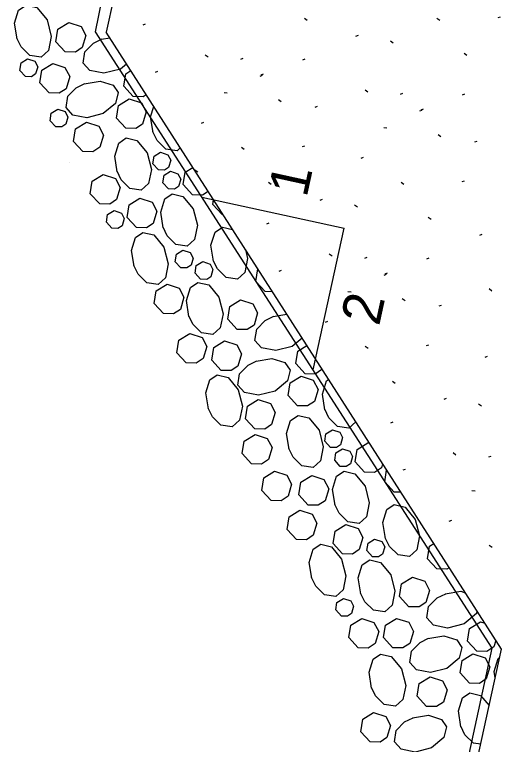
# Model space of a CAD drawing. Extents: x 2126110 to 2128246, y 1804858 to 1811658.
# Drawn here: x 2126783.7 to 2126845.4, y 1806501.5 to 1806594 of the extents above; entities that cross this region are included whole.
import ezdxf

# ---------------------------------------------------------------- set-up
doc = ezdxf.new("R2010")
doc.units = 0
doc.layers.add('1', color=7, linetype='Continuous')

msp = doc.modelspace()

# ---------------------------------------------------------------- linework, layer by layer
at = {"layer": '1'}
for p, q in [((2126793.902, 1806591.798), (2126800.031, 1806621.151)), ((2126801.607, 1806620.821), (2126795.259, 1806591.77)), ((2126820.761, 1806593.22), (2126820.408, 1806593.479)), ((2126837.578, 1806593.226), (2126837.226, 1806593.485)), ((2126844.984, 1806593.608), (2126845.283, 1806593.724)), ((2126799.944, 1806592.682), (2126800.242, 1806592.798)), ((2126844.245, 1806513.73), (2126793.902, 1806591.798)), ((2126845.409, 1806513.574), (2126795.259, 1806591.77)), ((2126794.663, 1806590.879), (2126795.72, 1806591.052)), ((2126826.961, 1806591.261), (2126827.259, 1806591.378)), ((2126831.684, 1806590.379), (2126831.331, 1806590.637)), ((2126808.202, 1806588.602), (2126807.849, 1806588.861)), ((2126841.023, 1806588.792), (2126840.671, 1806589.051)), ((2126812.358, 1806588.355), (2126812.657, 1806588.472)), ((2126820.207, 1806588.254), (2126820.505, 1806588.371)), ((2126801.508, 1806586.709), (2126801.806, 1806586.825)), ((2126814.813, 1806586.202), (2126815.111, 1806586.319)), ((2126814.95, 1806586.354), (2126815.248, 1806586.471)), ((2126810.224, 1806584.103), (2126810.624, 1806584.061)), ((2126828.465, 1806584.174), (2126828.112, 1806584.433)), ((2126832.621, 1806583.927), (2126832.919, 1806584.044)), ((2126817.469, 1806582.94), (2126817.117, 1806583.199)), ((2126840.469, 1806583.826), (2126840.768, 1806583.943)), ((2126821.771, 1806582.281), (2126822.069, 1806582.398)), ((2126835.076, 1806581.775), (2126835.374, 1806581.891)), ((2126835.212, 1806581.926), (2126835.511, 1806582.043)), ((2126807.355, 1806580.231), (2126807.653, 1806580.347)), ((2126830.486, 1806579.675), (2126830.886, 1806579.633)), ((2126837.732, 1806578.512), (2126837.379, 1806578.771)), ((2126842.033, 1806577.853), (2126842.332, 1806577.97)), ((2126812.775, 1806576.876), (2126812.422, 1806577.135)), ((2126820.181, 1806577.257), (2126820.479, 1806577.374)), ((2126827.618, 1806575.803), (2126827.916, 1806575.919)), ((2126790.616, 1806575.194), (2126790.628, 1806575.2)), ((2126806.881, 1806574.028), (2126806.528, 1806574.287)), ((2126840.444, 1806572.829), (2126840.742, 1806572.946)), ((2126816.22, 1806572.442), (2126815.868, 1806572.7)), ((2126833.038, 1806572.448), (2126832.685, 1806572.707)), ((2126807.4, 1806570.866), (2126825.446, 1806566.922)), ((2126822.42, 1806570.483), (2126822.719, 1806570.599)), ((2126827.143, 1806569.6), (2126826.791, 1806569.859)), ((2126810.091, 1806568.644), (2126809.99, 1806568.646)), ((2126815.666, 1806567.476), (2126815.964, 1806567.592)), ((2126836.483, 1806568.014), (2126836.13, 1806568.273)), ((2126821.523, 1806548.966), (2126825.446, 1806566.922)), ((2126842.683, 1806566.055), (2126842.981, 1806566.172)), ((2126823.924, 1806563.396), (2126823.572, 1806563.654)), ((2126828.08, 1806563.149), (2126828.379, 1806563.265)), ((2126835.929, 1806563.048), (2126836.227, 1806563.164)), ((2126817.23, 1806561.503), (2126817.529, 1806561.619)), ((2126830.535, 1806560.996), (2126830.833, 1806561.113)), ((2126830.672, 1806561.148), (2126830.97, 1806561.265)), ((2126844.187, 1806558.968), (2126843.834, 1806559.227)), ((2126816.356, 1806558.875), (2126815.429, 1806558.896)), ((2126825.946, 1806558.897), (2126826.346, 1806558.855)), ((2126833.191, 1806557.734), (2126832.839, 1806557.993)), ((2126837.493, 1806557.075), (2126837.791, 1806557.191)), ((2126816.461, 1806555.735), (2126818.189, 1806556.018)), ((2126823.077, 1806555.024), (2126823.376, 1806555.141)), ((2126828.497, 1806551.67), (2126828.145, 1806551.929)), ((2126835.903, 1806552.051), (2126836.202, 1806552.168)), ((2126843.34, 1806550.597), (2126843.638, 1806550.713)), ((2126831.942, 1806547.235), (2126831.59, 1806547.494)), ((2126838.143, 1806545.277), (2126838.441, 1806545.393)), ((2126842.865, 1806544.394), (2126842.513, 1806544.653)), ((2126831.388, 1806542.269), (2126831.687, 1806542.386)), ((2126839.646, 1806538.189), (2126839.294, 1806538.448)), ((2126843.803, 1806537.943), (2126844.101, 1806538.059)), ((2126832.952, 1806536.296), (2126833.251, 1806536.413)), ((2126832.641, 1806533.482), (2126831.789, 1806533.502)), ((2126841.668, 1806533.691), (2126842.068, 1806533.649)), ((2126838.799, 1806529.818), (2126839.098, 1806529.935)), ((2126844.219, 1806526.464), (2126843.867, 1806526.722)), ((2126821.033, 1806407.516), (2126844.245, 1806513.73)), ((2126822.044, 1806406.647), (2126845.409, 1806513.574))]:
    msp.add_line(p, q, dxfattribs=at)
for points in [[(2126783.979, 1806590.901), (2126783.651, 1806592.905), (2126784.167, 1806594.565), (2126785.107, 1806595.203), (2126786.476, 1806594.877), (2126787.77, 1806593.315), (2126788.301, 1806591.221), (2126787.943, 1806589.435), (2126787.013, 1806588.59), (2126785.576, 1806588.804), (2126784.486, 1806589.894), (2126783.947, 1806590.987)], [(2126790.087, 1806589.255), (2126788.902, 1806590.546), (2126789.155, 1806592.139), (2126790.528, 1806592.984), (2126792.082, 1806592.479), (2126792.678, 1806591.33), (2126792.226, 1806589.802), (2126791.358, 1806589.227), (2126790.088, 1806589.255)], [(2126797.851, 1806587.729), (2126797.076, 1806587.087), (2126794.982, 1806586.557), (2126793.197, 1806586.914), (2126792.351, 1806587.844), (2126792.566, 1806589.281), (2126793.655, 1806590.372), (2126794.747, 1806590.91)], [(2126785.043, 1806586.135), (2126784.332, 1806586.91), (2126784.484, 1806587.866), (2126785.308, 1806588.374), (2126786.239, 1806588.07), (2126786.597, 1806587.382), (2126786.326, 1806586.464), (2126785.805, 1806586.119), (2126785.044, 1806586.136)], [(2126788.052, 1806584.056), (2126786.866, 1806585.347), (2126787.12, 1806586.94), (2126788.493, 1806587.785), (2126790.047, 1806587.28), (2126790.642, 1806586.132), (2126790.191, 1806584.604), (2126789.323, 1806584.028), (2126788.053, 1806584.057)], [(2126798.7, 1806583.618), (2126797.513, 1806584.909), (2126797.767, 1806586.502), (2126798.391, 1806586.887)], [(2126792.493, 1806585.234), (2126794.495, 1806585.562), (2126796.157, 1806585.045), (2126796.794, 1806584.104), (2126796.468, 1806582.736), (2126794.906, 1806581.442), (2126792.812, 1806580.911), (2126791.027, 1806581.268), (2126790.181, 1806582.199), (2126790.396, 1806583.636), (2126791.484, 1806584.726), (2126792.577, 1806585.265)], [(2126797.754, 1806579.579), (2126796.568, 1806580.87), (2126796.822, 1806582.462), (2126798.194, 1806583.308), (2126799.748, 1806582.802), (2126800.344, 1806581.654), (2126799.893, 1806580.126), (2126799.025, 1806579.55), (2126797.755, 1806579.579)], [(2126800.345, 1806583.839), (2126799.97, 1806583.59), (2126798.7, 1806583.619)], [(2126801.223, 1806579.053), (2126800.895, 1806581.056), (2126801.299, 1806582.353)], [(2126788.868, 1806579.766), (2126788.157, 1806580.54), (2126788.309, 1806581.496), (2126789.133, 1806582.004), (2126790.065, 1806581.7), (2126790.422, 1806581.012), (2126790.151, 1806580.094), (2126789.63, 1806579.749), (2126788.869, 1806579.766)], [(2126792.324, 1806576.634), (2126791.138, 1806577.925), (2126791.392, 1806579.518), (2126792.765, 1806580.364), (2126794.318, 1806579.859), (2126794.914, 1806578.711), (2126794.463, 1806577.182), (2126793.595, 1806576.606), (2126792.324, 1806576.635)], [(2126804.662, 1806577.109), (2126804.258, 1806576.742), (2126802.821, 1806576.957), (2126801.731, 1806578.045), (2126801.192, 1806579.138)], [(2126796.681, 1806574.055), (2126796.354, 1806576.058), (2126796.87, 1806577.719), (2126797.811, 1806578.356), (2126799.179, 1806578.03), (2126800.473, 1806576.468), (2126801.004, 1806574.374), (2126800.647, 1806572.589), (2126799.717, 1806571.743), (2126798.279, 1806571.958), (2126797.19, 1806573.047), (2126796.651, 1806574.139)], [(2126801.909, 1806574.302), (2126801.197, 1806575.078), (2126801.35, 1806576.033), (2126802.173, 1806576.54), (2126803.106, 1806576.237), (2126803.463, 1806575.548), (2126803.192, 1806574.631), (2126802.671, 1806574.286), (2126801.909, 1806574.303)], [(2126803.174, 1806571.896), (2126802.462, 1806572.671), (2126802.615, 1806573.627), (2126803.438, 1806574.134), (2126804.371, 1806573.831), (2126804.729, 1806573.142), (2126804.457, 1806572.225), (2126803.937, 1806571.879), (2126803.174, 1806571.897)], [(2126806.239, 1806571.157), (2126805.054, 1806572.449), (2126805.307, 1806574.042), (2126806.255, 1806574.625)], [(2126794.445, 1806570.006), (2126793.258, 1806571.297), (2126793.512, 1806572.889), (2126794.885, 1806573.735), (2126796.439, 1806573.23), (2126797.035, 1806572.081), (2126796.583, 1806570.553), (2126795.715, 1806569.978), (2126794.445, 1806570.006)], [(2126802.516, 1806566.97), (2126802.189, 1806568.973), (2126802.705, 1806570.634), (2126803.646, 1806571.271), (2126805.014, 1806570.945), (2126806.308, 1806569.383), (2126806.839, 1806567.29), (2126806.482, 1806565.504), (2126805.552, 1806564.659), (2126804.114, 1806564.873), (2126803.025, 1806565.963), (2126802.486, 1806567.055)], [(2126808.202, 1806571.589), (2126807.51, 1806571.129), (2126806.241, 1806571.159)], [(2126799.107, 1806566.994), (2126797.921, 1806568.285), (2126798.175, 1806569.878), (2126799.548, 1806570.724), (2126801.102, 1806570.218), (2126801.698, 1806569.07), (2126801.246, 1806567.541), (2126800.378, 1806566.965), (2126799.108, 1806566.994)], [(2126809.99, 1806568.645), (2126808.804, 1806569.937), (2126808.895, 1806570.509)], [(2126796.006, 1806566.911), (2126795.295, 1806567.686), (2126795.447, 1806568.641), (2126796.271, 1806569.149), (2126797.203, 1806568.846), (2126797.56, 1806568.157), (2126797.289, 1806567.239), (2126796.768, 1806566.894), (2126796.007, 1806566.911)], [(2126808.894, 1806562.769), (2126808.567, 1806564.772), (2126809.082, 1806566.433), (2126810.023, 1806567.07), (2126811.294, 1806566.768)], [(2126798.809, 1806562.096), (2126798.481, 1806564.098), (2126798.998, 1806565.759), (2126799.939, 1806566.397), (2126801.307, 1806566.071), (2126802.601, 1806564.509), (2126803.132, 1806562.415), (2126802.775, 1806560.63), (2126801.845, 1806559.784), (2126800.407, 1806559.999), (2126799.318, 1806561.088), (2126798.778, 1806562.18)], [(2126804.749, 1806561.903), (2126804.037, 1806562.678), (2126804.19, 1806563.633), (2126805.013, 1806564.14), (2126805.946, 1806563.838), (2126806.303, 1806563.148), (2126806.032, 1806562.231), (2126805.511, 1806561.886), (2126804.749, 1806561.903)], [(2126812.931, 1806564.215), (2126813.217, 1806563.089), (2126812.859, 1806561.303), (2126811.929, 1806560.458), (2126810.492, 1806560.672), (2126809.402, 1806561.762), (2126808.863, 1806562.854)], [(2126807.257, 1806560.452), (2126806.545, 1806561.227), (2126806.698, 1806562.183), (2126807.521, 1806562.69), (2126808.454, 1806562.387), (2126808.812, 1806561.698), (2126808.54, 1806560.781), (2126808.019, 1806560.435), (2126807.257, 1806560.453)], [(2126815.429, 1806558.895), (2126814.242, 1806560.187), (2126814.496, 1806561.776)], [(2126805.777, 1806555.757), (2126805.449, 1806557.76), (2126805.965, 1806559.421), (2126806.906, 1806560.058), (2126808.274, 1806559.733), (2126809.569, 1806558.171), (2126810.1, 1806556.077), (2126809.742, 1806554.291), (2126808.812, 1806553.446), (2126807.375, 1806553.66), (2126806.284, 1806554.75), (2126805.746, 1806555.842)], [(2126802.549, 1806556.098), (2126801.362, 1806557.389), (2126801.617, 1806558.982), (2126802.989, 1806559.828), (2126804.543, 1806559.322), (2126805.139, 1806558.174), (2126804.687, 1806556.645), (2126803.819, 1806556.069), (2126802.549, 1806556.099)], [(2126811.886, 1806554.111), (2126810.7, 1806555.402), (2126810.954, 1806556.994), (2126812.326, 1806557.84), (2126813.88, 1806557.335), (2126814.476, 1806556.186), (2126814.024, 1806554.658), (2126813.156, 1806554.083), (2126811.887, 1806554.111)], [(2126820.133, 1806552.986), (2126818.874, 1806551.943), (2126816.781, 1806551.413), (2126814.995, 1806551.77), (2126814.149, 1806552.7), (2126814.364, 1806554.137), (2126815.453, 1806555.227), (2126816.546, 1806555.766)], [(2126805.433, 1806549.854), (2126804.246, 1806551.145), (2126804.501, 1806552.738), (2126805.873, 1806553.584), (2126807.427, 1806553.078), (2126808.023, 1806551.93), (2126807.571, 1806550.401), (2126806.703, 1806549.825), (2126805.433, 1806549.855)], [(2126809.851, 1806548.912), (2126808.664, 1806550.203), (2126808.919, 1806551.796), (2126810.291, 1806552.641), (2126811.845, 1806552.136), (2126812.441, 1806550.988), (2126811.989, 1806549.46), (2126811.121, 1806548.884), (2126809.851, 1806548.913)], [(2126820.498, 1806548.474), (2126819.312, 1806549.765), (2126819.565, 1806551.358), (2126820.721, 1806552.07)], [(2126814.291, 1806550.09), (2126816.294, 1806550.418), (2126817.955, 1806549.901), (2126818.592, 1806548.96), (2126818.266, 1806547.592), (2126816.704, 1806546.298), (2126814.61, 1806545.767), (2126812.825, 1806546.124), (2126811.979, 1806547.054), (2126812.194, 1806548.492), (2126813.283, 1806549.582), (2126814.375, 1806550.12)], [(2126822.648, 1806549.064), (2126822.636, 1806549.022), (2126821.768, 1806548.446), (2126820.498, 1806548.475)], [(2126808.233, 1806544.051), (2126807.906, 1806546.054), (2126808.421, 1806547.715), (2126809.362, 1806548.352), (2126810.731, 1806548.027), (2126812.025, 1806546.464), (2126812.556, 1806544.371), (2126812.198, 1806542.585), (2126811.268, 1806541.74), (2126809.831, 1806541.954), (2126808.741, 1806543.043), (2126808.202, 1806544.136)], [(2126819.552, 1806544.434), (2126818.366, 1806545.725), (2126818.62, 1806547.318), (2126819.993, 1806548.164), (2126821.547, 1806547.658), (2126822.143, 1806546.51), (2126821.691, 1806544.982), (2126820.823, 1806544.406), (2126819.553, 1806544.435)], [(2126823.021, 1806543.909), (2126822.694, 1806545.912), (2126823.21, 1806547.573), (2126823.485, 1806547.759)], [(2126814.122, 1806541.49), (2126812.936, 1806542.781), (2126813.19, 1806544.374), (2126814.563, 1806545.22), (2126816.117, 1806544.715), (2126816.713, 1806543.566), (2126816.261, 1806542.038), (2126815.393, 1806541.462), (2126814.123, 1806541.491)], [(2126826.928, 1806542.39), (2126826.057, 1806541.597), (2126824.619, 1806541.813), (2126823.53, 1806542.901), (2126822.991, 1806543.994)], [(2126818.48, 1806538.911), (2126818.152, 1806540.913), (2126818.669, 1806542.575), (2126819.609, 1806543.212), (2126820.978, 1806542.886), (2126822.271, 1806541.324), (2126822.803, 1806539.23), (2126822.446, 1806537.445), (2126821.515, 1806536.599), (2126820.077, 1806536.814), (2126818.988, 1806537.903), (2126818.449, 1806538.995)], [(2126813.72, 1806537.07), (2126812.534, 1806538.362), (2126812.788, 1806539.954), (2126814.16, 1806540.8), (2126815.714, 1806540.295), (2126816.31, 1806539.146), (2126815.859, 1806537.618), (2126814.991, 1806537.042), (2126813.72, 1806537.072)], [(2126823.707, 1806539.158), (2126822.995, 1806539.933), (2126823.148, 1806540.889), (2126823.971, 1806541.396), (2126824.904, 1806541.093), (2126825.262, 1806540.404), (2126824.991, 1806539.487), (2126824.47, 1806539.141), (2126823.708, 1806539.159)], [(2126828.038, 1806536.013), (2126826.852, 1806537.305), (2126827.106, 1806538.898), (2126828.478, 1806539.743), (2126828.665, 1806539.683)], [(2126824.973, 1806536.752), (2126824.261, 1806537.527), (2126824.413, 1806538.483), (2126825.237, 1806538.99), (2126826.169, 1806538.687), (2126826.527, 1806537.998), (2126826.256, 1806537.081), (2126825.735, 1806536.735), (2126824.973, 1806536.753)], [(2126830.331, 1806537.084), (2126830.176, 1806536.561), (2126829.308, 1806535.985), (2126828.039, 1806536.015)], [(2126816.199, 1806532.419), (2126815.013, 1806533.71), (2126815.267, 1806535.303), (2126816.639, 1806536.149), (2126818.194, 1806535.643), (2126818.79, 1806534.495), (2126818.338, 1806532.966), (2126817.47, 1806532.391), (2126816.2, 1806532.419)], [(2126824.315, 1806531.826), (2126823.987, 1806533.829), (2126824.503, 1806535.49), (2126825.444, 1806536.127), (2126826.812, 1806535.801), (2126828.106, 1806534.239), (2126828.638, 1806532.146), (2126828.28, 1806530.36), (2126827.35, 1806529.515), (2126825.912, 1806529.729), (2126824.823, 1806530.818), (2126824.284, 1806531.911)], [(2126831.789, 1806533.501), (2126830.602, 1806534.793), (2126830.841, 1806536.29)], [(2126820.906, 1806531.849), (2126819.719, 1806533.141), (2126819.974, 1806534.734), (2126821.346, 1806535.579), (2126822.9, 1806535.074), (2126823.496, 1806533.926), (2126823.044, 1806532.397), (2126822.176, 1806531.821), (2126820.906, 1806531.85)], [(2126830.693, 1806527.625), (2126830.365, 1806529.627), (2126830.881, 1806531.289), (2126831.821, 1806531.926), (2126833.19, 1806531.6), (2126834.484, 1806530.038), (2126835.016, 1806527.945), (2126834.658, 1806526.159), (2126833.728, 1806525.314), (2126832.29, 1806525.528), (2126831.2, 1806526.617), (2126830.661, 1806527.71)], [(2126819.398, 1806527.466), (2126818.212, 1806528.758), (2126818.466, 1806530.35), (2126819.839, 1806531.196), (2126821.393, 1806530.691), (2126821.989, 1806529.542), (2126821.537, 1806528.014), (2126820.669, 1806527.438), (2126819.399, 1806527.467)], [(2126825.234, 1806525.673), (2126824.048, 1806526.964), (2126824.302, 1806528.557), (2126825.674, 1806529.403), (2126827.228, 1806528.897), (2126827.824, 1806527.749), (2126827.373, 1806526.22), (2126826.504, 1806525.644), (2126825.234, 1806525.674)], [(2126821.352, 1806522.579), (2126821.024, 1806524.582), (2126821.54, 1806526.242), (2126822.481, 1806526.88), (2126823.849, 1806526.554), (2126825.143, 1806524.991), (2126825.674, 1806522.898), (2126825.317, 1806521.113), (2126824.387, 1806520.267), (2126822.949, 1806520.482), (2126821.86, 1806521.571), (2126821.321, 1806522.664)], [(2126829.056, 1806525.308), (2126828.344, 1806526.083), (2126828.496, 1806527.039), (2126829.32, 1806527.546), (2126830.252, 1806527.243), (2126830.61, 1806526.554), (2126830.339, 1806525.636), (2126829.817, 1806525.291), (2126829.056, 1806525.309)], [(2126837.227, 1806523.751), (2126836.041, 1806525.043), (2126836.295, 1806526.635), (2126836.824, 1806526.961)], [(2126827.575, 1806520.613), (2126827.248, 1806522.616), (2126827.763, 1806524.277), (2126828.704, 1806524.914), (2126830.072, 1806524.589), (2126831.367, 1806523.027), (2126831.898, 1806520.933), (2126831.54, 1806519.147), (2126830.61, 1806518.302), (2126829.173, 1806518.516), (2126828.083, 1806519.606), (2126827.544, 1806520.698)], [(2126838.78, 1806523.911), (2126838.497, 1806523.723), (2126837.227, 1806523.752)], [(2126833.684, 1806518.967), (2126832.498, 1806520.257), (2126832.752, 1806521.85), (2126834.124, 1806522.696), (2126835.678, 1806522.19), (2126836.275, 1806521.042), (2126835.823, 1806519.514), (2126834.955, 1806518.938), (2126833.685, 1806518.967)], [(2126842.31, 1806518.407), (2126842.235, 1806518.094), (2126840.672, 1806516.799), (2126838.579, 1806516.269), (2126836.794, 1806516.626), (2126835.948, 1806517.556), (2126836.163, 1806518.993), (2126837.251, 1806520.083), (2126838.344, 1806520.622)], [(2126838.26, 1806520.591), (2126840.262, 1806520.919), (2126840.808, 1806520.749)], [(2126825.103, 1806517.789), (2126824.391, 1806518.564), (2126824.544, 1806519.519), (2126825.367, 1806520.027), (2126826.299, 1806519.724), (2126826.657, 1806519.035), (2126826.386, 1806518.117), (2126825.865, 1806517.772), (2126825.103, 1806517.79)], [(2126827.251, 1806513.758), (2126826.065, 1806515.049), (2126826.319, 1806516.642), (2126827.691, 1806517.487), (2126829.245, 1806516.982), (2126829.841, 1806515.833), (2126829.39, 1806514.305), (2126828.521, 1806513.729), (2126827.251, 1806513.759)], [(2126831.649, 1806513.768), (2126830.463, 1806515.059), (2126830.717, 1806516.652), (2126832.089, 1806517.497), (2126833.643, 1806516.992), (2126834.239, 1806515.844), (2126833.788, 1806514.315), (2126832.92, 1806513.74), (2126831.649, 1806513.769)], [(2126842.296, 1806513.33), (2126841.11, 1806514.621), (2126841.364, 1806516.214), (2126842.737, 1806517.06), (2126843.289, 1806516.88)], [(2126836.09, 1806514.946), (2126838.092, 1806515.273), (2126839.753, 1806514.757), (2126840.391, 1806513.816), (2126840.065, 1806512.448), (2126838.502, 1806511.154), (2126836.409, 1806510.623), (2126834.623, 1806510.98), (2126833.777, 1806511.91), (2126833.992, 1806513.348), (2126835.081, 1806514.437), (2126836.174, 1806514.976)], [(2126844.681, 1806514.71), (2126844.434, 1806513.877), (2126843.566, 1806513.302), (2126842.297, 1806513.331)], [(2126828.944, 1806508.671), (2126828.616, 1806510.674), (2126829.132, 1806512.334), (2126830.072, 1806512.972), (2126831.441, 1806512.647), (2126832.735, 1806511.084), (2126833.267, 1806508.99), (2126832.909, 1806507.205), (2126831.978, 1806506.359), (2126830.541, 1806506.573), (2126829.451, 1806507.663), (2126828.912, 1806508.756)], [(2126841.351, 1806509.29), (2126840.164, 1806510.581), (2126840.419, 1806512.174), (2126841.791, 1806513.02), (2126843.345, 1806512.514), (2126843.941, 1806511.366), (2126843.49, 1806509.838), (2126842.621, 1806509.262), (2126841.352, 1806509.291)], [(2126844.622, 1806509.971), (2126844.492, 1806510.768), (2126845.008, 1806512.429), (2126845.185, 1806512.549)], [(2126835.921, 1806506.346), (2126834.734, 1806507.637), (2126834.989, 1806509.23), (2126836.361, 1806510.076), (2126837.915, 1806509.57), (2126838.511, 1806508.422), (2126838.06, 1806506.893), (2126837.191, 1806506.318), (2126835.921, 1806506.347)], [(2126840.278, 1806503.767), (2126839.95, 1806505.769), (2126840.467, 1806507.431), (2126841.408, 1806508.068), (2126842.776, 1806507.742), (2126843.851, 1806506.443)], [(2126828.755, 1806501.841), (2126827.569, 1806503.133), (2126827.822, 1806504.725), (2126829.195, 1806505.571), (2126830.749, 1806505.065), (2126831.345, 1806503.917), (2126830.893, 1806502.389), (2126830.025, 1806501.813), (2126828.755, 1806501.842)], [(2126834.14, 1806504.88), (2126836.142, 1806505.209), (2126837.803, 1806504.692), (2126838.442, 1806503.751), (2126838.115, 1806502.383), (2126836.553, 1806501.089), (2126834.46, 1806500.558), (2126832.674, 1806500.915), (2126831.828, 1806501.846), (2126832.043, 1806503.283), (2126833.132, 1806504.373), (2126834.225, 1806504.912)], [(2126842.779, 1806501.535), (2126841.876, 1806501.67), (2126840.787, 1806502.759), (2126840.247, 1806503.851)]]:
    msp.add_lwpolyline(points, dxfattribs=at)

# ---------------------------------------------------------------- texts
for s, p in [('1', (2126820.688, 1806570.704)), ('2', (2126829.881, 1806554.425))]:
    msp.add_text(s, height=5, rotation=77.67359, dxfattribs=at).set_placement(p)

doc.saveas('drawing.dxf')
